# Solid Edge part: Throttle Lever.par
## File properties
Author: m_hel
Template: iso metric part.par
Last saved by: m_hel
Revision: 5
Application: Solid Edge
Accuracy: 0,990
Username: m_hel
Material: Chrome
Face Style: Chrome
Fill Style: Normal
Virtual Style: Normal
Grouping: Uncategorized
LibraryName: Custom Materials
Coef. of Thermal Exp: 0.0
Thermal Conductivity: 0.0
Specific Heat: 0.0
Modulus of Elasticity: 0.0
Poisson's Ratio: 0.0
Yield Stress: 0.0
Ultimate Stress: 0.0
Elongation: 0.0
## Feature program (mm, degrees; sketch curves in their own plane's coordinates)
sketch for "unnamed Protrusion 1" plane through (0, 0, 0) normal (1, 0, 0) x-axis (0, 1, 0)
  circle centre (0, 0) radius 25
extrude "unnamed Protrusion 1" add finite 20 along -normal
sketch for "ExtrudedProtrusion_2" plane through (0, 0, 0) normal (1, 0, 0) x-axis (0, 1, 0)
  arc centre (0, 134.422) radius 12.5 from (-12.5, 134.422) to (12.5, 134.422) cw
  line (12.5, 124.422) -> (12.5, 134.422)
  arc centre (0, 124.422) radius 12.5 from (-12.5, 124.422) to (12.5, 124.422) ccw
  line (-12.5, 134.422) -> (-12.5, 124.422)
extrude "ExtrudedProtrusion_2" add finite 120 along +normal  FiniteDepth2 = 20 mm
swept protrusion "SweptProtrusion_1"
fillet "Round_2" radius 10
fillet "Round_3" radius 4.5
sketch for "ExtrudedProtrusion_3" plane through (0, 0, 0) normal (1, 0, 0) x-axis (0, 1, 0)
  circle centre (0, 0) radius 15
extrude "ExtrudedProtrusion_3" add finite 50 along +normal
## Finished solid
Body 1: solid body, 47 faces, 106 edges, 61 vertices.
  Faces by surface: spline 18, blend 10, cylinder 8, plane 7, torus 4
  Edges by curve: circle 33, intersection 31, spline 26, line 12, curve on surface 4
Bounding box of the edges (mm; curved faces can reach further): 140.000 x 50.000 x 171.922, from (-20, -25, -25) to (120, 25, 146.922).
Cylindrical faces by radius (mm): R10 x4, R12.5 x2, R15 x1, R25 x1
Toroidal faces (ring radius, tube radius in mm): R2.5 r10 x4
Planar faces by outward normal: +x 3, +y 1, -x 2, -y 1
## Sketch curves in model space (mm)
ellipse centre (-8.8219, 0, 46.1333) radii 15, 7.5
circle centre (21.2402, 0, 129.422) radius 12.5
arc centre (-15, 20, 0) radius 5 from (-15, 25, 0) through (-18.6369, 23.4312, 0) to (-20, 20, 0)
line (-20, 20, 0) -> (-20, -20, 0)
arc centre (-15, -20, 0) radius 5 from (-20, -20, 0) through (-18.4312, -23.6369, 0) to (-15, -25, 0)
line (-15, -25, 0) -> (-5, -25, 0)
arc centre (-5, -20, 0) radius 5 from (-5, -25, 0) through (-1.3631, -23.4312, 0) to (0, -20, 0)
line (0, -20, 0) -> (0, 20, 0)
arc centre (-5, 20, 0) radius 5 from (-5, 25, 0) through (-1.3631, 23.4312, 0) to (0, 20, 0)
line (-5, 25, 0) -> (-15, 25, 0)
arc centre (180.1381, 0, 25) radius 190.1381 from (-10, 0, 25) through (-2.0226, 0, 79.4975) to (21.2402, 0, 129.422)
line (-10, 0, 0) -> (-10, 0, 25)
arc centre (0, 0, 134.422) radius 12.5 from (0, -12.5, 134.422) through (0, 0.3704, 146.9165) to (0, 12.5, 134.422)
line (0, -12.5, 134.422) -> (0, -12.5, 124.422)
arc centre (0, 0, 124.422) radius 12.5 from (0, -12.5, 124.422) through (0, 0.3704, 111.9275) to (0, 12.5, 124.422)
line (0, 12.5, 124.422) -> (0, 12.5, 134.422)
circle centre (0, 0, 0) radius 25
circle centre (0, 0, 0) radius 15
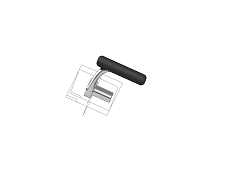
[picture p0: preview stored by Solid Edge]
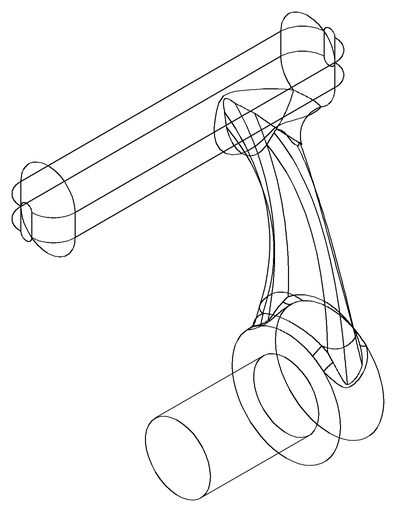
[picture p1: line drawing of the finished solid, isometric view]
